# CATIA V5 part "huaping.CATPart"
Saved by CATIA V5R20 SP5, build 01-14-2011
Part number: 花瓶
Material "Wallpaper Strip 1": density 2120 kg/m3, Young's modulus 2.56e+10 Pa, Poisson ratio 0.22
Material "Summer sky"
Material "DS Red": density 7860 kg/m3, Young's modulus 2e+11 Pa, Poisson ratio 0.266
Material "Cloudy Sky"
Bounding box of the stored display mesh (mm): x -34.997 to 34.997, y -35.695 to 35.695, z -0.051 to 134.067
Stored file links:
  D:\请勿打开\嗯嗯\别打开了\嗯哼\不听？\180122236\180122236邓慈鑫\huaping.CATPart
  C:\Program Files\Dassault Systemes\B20\intel_a\startup\materials\Catalog.CATMaterial
  C:\Program Files\Dassault Systemes\B20\intel_a\startup\materials\chessboard.jpg
  C:\Program Files\Dassault Systemes\B20\intel_a\startup\materials\DS_star.jpg
  C:\Program Files\Dassault Systemes\B20\intel_a\startup\materials\red_env_512x512.jpg
  C:\Program Files\Dassault Systemes\B20\intel_a\startup\materials\walnut.jpg
  C:\Program Files\Dassault Systemes\B20\intel_a\startup\materials\yellow_env_512x512.jpg
  C:\Program Files\Dassault Systemes\B20\intel_a\startup\materials\red_wood.jpg
  C:\Program Files\Dassault Systemes\B20\intel_a\startup\materials\alcantara.jpg
  C:\Program Files\Dassault Systemes\B20\intel_a\startup\materials\beige_leather.jpg
  C:\Program Files\Dassault Systemes\B20\intel_a\startup\materials\green_leather.jpg
  C:\Program Files\Dassault Systemes\B20\intel_a\startup\materials\summer_sky.jpg
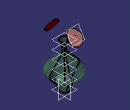
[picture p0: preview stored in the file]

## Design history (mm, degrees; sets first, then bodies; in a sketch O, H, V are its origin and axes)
Body1 (main body), material "Wallpaper Strip 1"
  Plane1: type Offset, RefPlane xy-plane, Offset 20
  Plane2: type Offset, RefPlane Plane1, Offset 20
  Plane3: type Offset, RefPlane Plane2, Offset 20
  Plane4: type Offset, RefPlane Plane3, Offset 20
  Plane5: type Offset, RefPlane Plane4, Offset 20
  Sketch1 on xy-plane, origin (0, 0, 0), H (1, 0, 0), V (0, 1, 0)
    circle A1 centre (0, 0) radius 10
  Sketch2 on Plane1, origin (0, 0, 20), H (1, 0, 0), V (0, 1, 0)
    circle A1 centre (0, 0) radius 20
  Sketch3 on Plane2, origin (0, 0, 40), H (1, 0, 0), V (0, 1, 0)
    circle A1 centre (0, 0) radius 35
  Sketch4 on Plane3, origin (0, 0, 60), H (1, 0, 0), V (0, 1, 0)
    circle A1 centre (0, 0) radius 20
  Sketch5 on Plane4, origin (0, 0, 80), H (1, 0, 0), V (0, 1, 0)
    circle A1 centre (0, 0) radius 5
  Sketch6 on Plane5, origin (0, 0, 100), H (1, 0, 0), V (0, 1, 0)
    circle A1 centre (0, 0) radius 10
  Loft1: solid, Sections (Sketch1; Sketch2; Sketch3; Sketch4; Sketch5; Sketch6)
  Shell1: ExtOffset 0, Face face of Loft1, IntOffset 1
  Sketch7 on yz-plane, origin (0, 0, 0), H (0, 1, 0), V (0, 0, 1)
    axis line L1 (0, 0) -> (0, 29.7212)
    line L2 (0, 0) -> (0, 20.1202)
    line L3 (0, 20.1202) -> (16.3337, 20.1202)
    line L4 (16.3337, 20.1202) -> (9.3439, 2.1572)
    line L5 (9.3439, 2.1572) -> (0, 1.2281)
    point P5 (0, 1.2281)
    line L6 (0, 1.2281) -> (0, 2.1572)
    vertical: L1 V, L2 V, L6 V
    horizontal: L3 H
    coincidence: P5 L1
Body2, material "Summer sky"
  Sketch8 on yz-plane, origin (0, 0, 0), H (0, 1, 0), V (0, 0, 1)
    axis line L1 (0, 0) -> (0, 30.1857)
    line L2 (0, 0) -> (0, 19.0363)
    line L3 (0, 19.0363) -> (15.2464, 19.0363)
    line L4 (15.2464, 19.0363) -> (9.1886, 0)
    point P4 (9.1886, 0)
    line L5 (9.1886, 0) -> (0, 0)
    vertical: L1 V, L2 V
    horizontal: L3 H, L5 H
    coincidence: P4 H
  Shaft1: profile Sketch8, axis Sketch8.L1, angle 360
Body3, material "Cloudy Sky"
  Sketch9 on yz-plane, origin (0, 0, 0), H (0, 1, 0), V (0, 0, 1)
    spline S1 through (0, 0) (0, 59.8902) (8.0727, 104.7188) (25.6044, 121.7116)
    point P1 (0, 0)
    point P2 (0, 59.8902)
    coincidence: P1 O, P2 V
  Plane6: type Normal, Curve Sketch9, RefPoint vertex of Sketch9
  Sketch10 on Plane6, origin (0, 72.2974, 42.7547), H (1, 0, 0), V (0, -0.509, 0.8608)
    circle A1 centre (0, 91.5284) radius 0.5
    point P1 (0, 91.5284)
    coincidence: P1 V
  Rib1: profile Sketch10, centre curve Sketch9
Body4, material "DS Red"
  Sketch11 on Plane6, origin (0, 72.2974, 42.7547), H (1, 0, 0), V (0, -0.509, 0.8608)
    spline S1 through (-10.9157, 92.9134) (12.7019, 103.5979) (15.6789, 82.031) (-6.9464, 74.1165) (-13.2973, 86.9775) (-10.9157, 92.9134)
    point P1 (-10.9157, 92.9134)
    point P2 (-10.9157, 92.9134)
    coincidence: P1 P2
  Pad1: profile Sketch11, direction (0, -0.8608, -0.509), length 2
  Mirror1: of the body so far, about zx-plane
  Mirror2: of the body so far, about zx-plane
Body5, material "无"
Body6, material "无"
Body7, material "无"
